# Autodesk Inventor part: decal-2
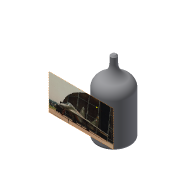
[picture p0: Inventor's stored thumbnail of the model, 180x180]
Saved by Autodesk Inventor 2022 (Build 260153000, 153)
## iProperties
Part Number: decal-2
Document SubType Name: Modeling
Created: 2002-12
Designer: deepak
Material: Generic
Density: 1 g/cm^3
Appearance: Default
Control State: 0
Master: False
Checked Out: False
Shininess: 64.0
Length Units: 11269
Angle Units: 11279
Time Units: 11290
Mass Units: 11283
Length Display Precision: 3
Angle Display Precision: 2
Compacted: True
Density: 0.0
Volumn: 0.0
Area: 0.0
PropertySet Name: Model Information
Author: deepak
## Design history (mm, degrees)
node "Sketch1"
sketch "Sketch2"
  geometry: L1 (2.054, 26.655)-(2.054, 21.177); L2 (11.64, 6.114)-(11.64, -24.209); L3 (11.64, -24.209)-(-0.098, -24.209); L4 (-0.098, -24.209)-(-0.098, 26.655); L5 (-0.098, 26.655)-(2.054, 26.655); A1 r 9.502 centre (11.556, 21.177) between (2.054, 21.177) and (7.532, 12.57); A2 r 7.127 centre (4.514, 6.114) between (11.64, 6.114) and (7.532, 12.57)
  constraints: 10 end point, 4 point on circle, 3 parallel, 3 tangent, 2 centre point, 1 perpendicular, 1 vertical
revolve "Revolution1" sketch "Sketch2" stored, may be unused: angle "d0" = 90 deg
fillet "Fillet1" dims "d1" = 2
chamfer "Chamfer1" distance "d2" = 1; stored, may be unused: second distance "d3" = 2, angle "d21" = 45 deg
workplane "Work Plane4"
sketch "Sketch7"
  geometry: L1 (-11.326, 14.075)-(33.849, 14.075); L2 (33.849, 14.075)-(33.849, -10.781); L3 (33.849, -10.781)-(-11.326, -10.781); L4 (-11.326, -10.781)-(-11.326, 14.075); 1 further point; 1 other entity
  constraints: 2 other
  node "Image6"
body "Solid1"
